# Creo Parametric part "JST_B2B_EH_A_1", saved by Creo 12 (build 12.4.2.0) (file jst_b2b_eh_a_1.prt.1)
Units: Custom; MM, KILOGRAM, SECS

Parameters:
  PTC_WM_ITERATION = "0"
  PTC_WM_VERSION = "-.0"
  PTC_WM_LIFECYCLE_STATE = "In Work"
  PTC_WM_LIFECYCLE = "MO_CADDocument"
  PTC_WM_CREATED_BY = "Maximilian Roepper (Z0017RMS: MO)"
  PTC_WM_CREATED_ON = "18-Sep-26 11:36:42 AM"
  PTC_WM_MODIFIED_BY = "Maximilian Roepper (Z0017RMS: MO)"
  PTC_WM_MODIFIED_ON = "18-Sep-26 11:36:46 AM"
  PDMLINKNUMBER = "PDM000071454896"
  PTC_WM_NAME = "jst_b2b_eh_a_1.prt"
  PTC_WM_NUMBER = "PDM000071454896"

Other parameters: WEIGHT, WEIGHT_FACTOR, WEIGHT_ADD, _MASS_TEMP, _DIFF_TEMP, MC_ERRORS, SUPPLIER

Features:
  1. coordinate system
  2. datum plane "PRT_YZ"
  3. datum plane "PRT_XY"
  4. datum plane "PRT_XZ"
  5. coordinate system
  6. datum axis
  7. datum axis
  8. datum axis
  9. coordinate system
  10. imported feature

Other named items: PRT, SIEMENS_MO, DRW_VIEW_ORG, PRT_X, PRT_Y, PRT_Z, CS0, ROUGH_GROB

Layers: 00_STD_CSYS-KSYS, 01_STD_PLANES-EBENEN, 02_STD_AXES-ACHSEN, 03_STD_CSYS-KSYS, 24_IMPORT_FEAT-IMPORT_KE

Surfaces: 82 plane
